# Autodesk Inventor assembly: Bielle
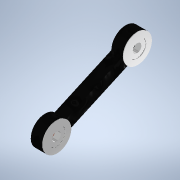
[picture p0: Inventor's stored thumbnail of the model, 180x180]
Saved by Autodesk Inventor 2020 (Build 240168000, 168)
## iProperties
Created: 2023-10
Part Number: Bielle
Document SubType Name: Assembly
Designer: bruno
Author: bruno
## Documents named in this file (5)
- C:\Users\bruno\Documents\1-Cours-2023-24\Maquettes-Inventor\Pince-robot-Dobot\Bielle.iam
- C:\Users\bruno\Documents\1-Cours-2023-24\Maquettes-Inventor\Pince-robot-Dobot\bielle.ipt
- C:\Users\bruno\Documents\1-Cours-2023-24\Maquettes-Inventor\Pince-robot-Dobot\HS422\coussinet-bielle.ipt
- C:\Users\bruno\Documents\1-Cours-2023-24\Maquettes-Inventor\Pince-robot-Dobot\Rondelle.ipt
- C:\Users\bruno\Documents\1-Cours-2023-24\Maquettes-Inventor\Pince-robot-Dobot\Rondelle-2.ipt
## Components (5 placed, 4 different names)
1. bielle:1 — Logement:1, Logement:2, Logement:4
2. coussinet-bielle:1 — Logement:2, Logement:3
3. coussinet-bielle:2 — Logement:1
4. Rondelle:1 — Logement:3
5. Rondelle-2:1 — Logement:4
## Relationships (4: Insert 4)
- Logement:1 [Insert]: bielle:1 ↔ coussinet-bielle:2
- Logement:2 [Insert]: bielle:1 ↔ coussinet-bielle:1
- Logement:3 [Insert]: coussinet-bielle:1 ↔ Rondelle:1
- Logement:4 [Insert]: bielle:1 ↔ Rondelle-2:1
